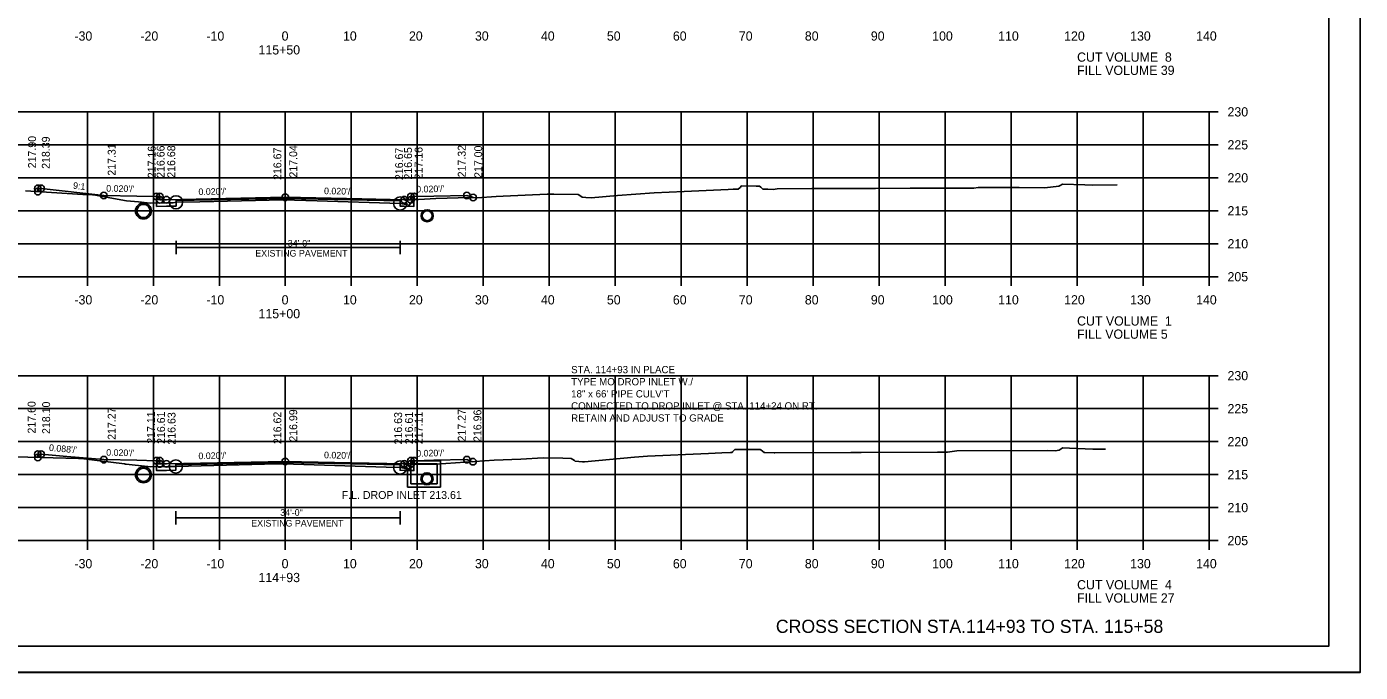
# Model space of a CAD drawing. Extents: x 1368968 to 1369915, y 377395 to 380381.
# Drawn here: x 1369712.6 to 1369914.7, y 378674.7 to 378772.6 of the extents above; entities that cross this region are included whole.
import ezdxf

# ---------------------------------------------------------------- set-up
doc = ezdxf.new("R2010")
doc.units = 0
for name, color, linetype in [('Default', 7, 'Continuous'), ('S_BORDER_NO_PLOT', 7, 'Continuous'), ('S_BREAKLINE_ANNOT', 7, 'Continuous'), ('S_BRIDGE', 7, 'Continuous'), ('S_BRIDGE_ANNOT', 7, 'Continuous'), ('S_CONTOUR_MAJOR', 7, 'Continuous'), ('S_CONTOUR_MINOR', 7, 'Continuous'), ('S_CROSS_DRAIN', 7, 'Continuous'), ('S_CTL_TABLE', 7, 'Continuous'), ('S_CURB_ANNOT', 7, 'Continuous'), ('S_DITCHLINE_ANNOT', 7, 'Continuous'), ('S_DROP_INLET', 7, 'Continuous'), ('S_EXIST_ROW_ANNOT', 7, 'Continuous'), ('S_EXISTING_ALIGNMENT_ANNOT', 7, 'Continuous'), ('S_FENCE', 7, 'Continuous')]:
    doc.layers.add(name, color=color, linetype=linetype)

msp = doc.modelspace()

# ---------------------------------------------------------------- linework, layer by layer
at = {"layer": 'Default'}
for p, q in [((1369735.22, 378746.24), (1369735.22, 378745.41)), ((1369735.18, 378706.19), (1369735.18, 378705.36)), ((1369770.78, 378703.31), (1369774.78, 378703.31)), ((1369770.28, 378702.81), (1369775.28, 378702.81))]:
    msp.add_line(p, q, dxfattribs=at)
at = {"layer": 'S_BORDER_NO_PLOT'}
for points in [[(1369732.27, 378746.86), (1369732.28, 378745.35), (1369733.78, 378745.38), (1369735.22, 378745.41), (1369735.22, 378746.24), (1369751.78, 378746.57), (1369769.19, 378746.22), (1369769.19, 378745.39), (1369769.78, 378745.38), (1369771.28, 378745.35), (1369771.29, 378746.86)], [(1369732.27, 378706.81), (1369732.28, 378705.3), (1369733.78, 378705.33), (1369735.18, 378705.36), (1369735.18, 378706.19), (1369751.78, 378706.52), (1369769.18, 378706.18), (1369769.18, 378705.35), (1369769.78, 378705.33), (1369771.28, 378705.3), (1369771.29, 378706.81)]]:
    msp.add_lwpolyline(points, dxfattribs=at)
at = {"layer": 'S_BREAKLINE_ANNOT'}
for p, q in [((1369891.78, 378734.7), (1369891.78, 378759.7)), ((1369893.18, 378759.7), (1369891.78, 378759.7)), ((1369893.18, 378754.7), (1369891.78, 378754.7)), ((1369893.18, 378749.7), (1369891.78, 378749.7)), ((1369893.18, 378744.7), (1369891.78, 378744.7)), ((1369893.18, 378739.7), (1369891.78, 378739.7)), ((1369611.78, 378734.7), (1369891.78, 378734.7)), ((1369721.78, 378733.3), (1369721.78, 378734.7)), ((1369731.78, 378733.3), (1369731.78, 378734.7)), ((1369741.78, 378733.3), (1369741.78, 378734.7)), ((1369751.78, 378733.3), (1369751.78, 378734.7)), ((1369761.78, 378733.3), (1369761.78, 378734.7)), ((1369771.78, 378733.3), (1369771.78, 378734.7)), ((1369781.78, 378733.3), (1369781.78, 378734.7)), ((1369791.78, 378733.3), (1369791.78, 378734.7)), ((1369801.78, 378733.3), (1369801.78, 378734.7)), ((1369811.78, 378733.3), (1369811.78, 378734.7)), ((1369821.78, 378733.3), (1369821.78, 378734.7)), ((1369831.78, 378733.3), (1369831.78, 378734.7)), ((1369841.78, 378733.3), (1369841.78, 378734.7)), ((1369851.78, 378733.3), (1369851.78, 378734.7)), ((1369861.78, 378733.3), (1369861.78, 378734.7)), ((1369871.78, 378733.3), (1369871.78, 378734.7)), ((1369881.78, 378733.3), (1369881.78, 378734.7)), ((1369891.78, 378733.3), (1369891.78, 378734.7)), ((1369893.18, 378734.7), (1369891.78, 378734.7)), ((1369891.78, 378694.7), (1369891.78, 378719.7)), ((1369893.18, 378719.7), (1369891.78, 378719.7)), ((1369893.18, 378714.7), (1369891.78, 378714.7)), ((1369893.18, 378709.7), (1369891.78, 378709.7)), ((1369893.18, 378704.7), (1369891.78, 378704.7)), ((1369893.18, 378699.7), (1369891.78, 378699.7)), ((1369611.78, 378694.7), (1369891.78, 378694.7)), ((1369721.78, 378693.3), (1369721.78, 378694.7)), ((1369731.78, 378693.3), (1369731.78, 378694.7)), ((1369741.78, 378693.3), (1369741.78, 378694.7)), ((1369751.78, 378693.3), (1369751.78, 378694.7)), ((1369761.78, 378693.3), (1369761.78, 378694.7)), ((1369771.78, 378693.3), (1369771.78, 378694.7)), ((1369781.78, 378693.3), (1369781.78, 378694.7)), ((1369791.78, 378693.3), (1369791.78, 378694.7)), ((1369801.78, 378693.3), (1369801.78, 378694.7)), ((1369811.78, 378693.3), (1369811.78, 378694.7)), ((1369821.78, 378693.3), (1369821.78, 378694.7)), ((1369831.78, 378693.3), (1369831.78, 378694.7)), ((1369841.78, 378693.3), (1369841.78, 378694.7)), ((1369851.78, 378693.3), (1369851.78, 378694.7)), ((1369861.78, 378693.3), (1369861.78, 378694.7)), ((1369871.78, 378693.3), (1369871.78, 378694.7)), ((1369881.78, 378693.3), (1369881.78, 378694.7)), ((1369891.78, 378693.3), (1369891.78, 378694.7)), ((1369893.18, 378694.7), (1369891.78, 378694.7))]:
    msp.add_line(p, q, dxfattribs=at)
at = {"layer": 'S_BRIDGE_ANNOT'}
for q in [(1369909.96, 378884.16), (1369593.78, 378678.7)]:
    msp.add_line((1369909.96, 378678.7), q, dxfattribs=at)
at = {"layer": 'S_CROSS_DRAIN'}
for p, q in [((1369735.22, 378739.12), (1369769.19, 378739.12)), ((1369735.18, 378698.15), (1369769.18, 378698.15))]:
    msp.add_line(p, q, dxfattribs=at)
at = {"layer": 'S_CTL_TABLE'}
for points in [[(1369712.41, 378747.72), (1369721.09, 378747.15), (1369722.55, 378747.11), (1369722.6, 378747.11), (1369723, 378747.06), (1369723.51, 378746.99), (1369727.72, 378746.23), (1369729.53, 378746.07), (1369731.31, 378745.86), (1369733.76, 378745.93), (1369734.77, 378745.9), (1369735.22, 378745.99), (1369738.81, 378746.07), (1369751.45, 378746.38), (1369756.6, 378746.22), (1369769.19, 378745.81), (1369770.12, 378745.63), (1369770.57, 378745.57), (1369770.75, 378745.8), (1369771.1, 378746.34), (1369773.74, 378746.5), (1369774.61, 378746.54), (1369779.7, 378746.72), (1369780.86, 378746.68), (1369783.76, 378746.87), (1369784.81, 378746.92), (1369791.45, 378747.24), (1369792.46, 378747.22), (1369796.14, 378747.19), (1369796.4, 378747.01), (1369796.75, 378746.74), (1369797.32, 378746.7), (1369798.15, 378746.66), (1369802.11, 378747.03), (1369807.68, 378747.41), (1369812.23, 378747.63), (1369818.92, 378747.94), (1369819.67, 378747.96), (1369820.42, 378747.99), (1369820.71, 378748.24), (1369820.91, 378748.47), (1369823.15, 378748.45), (1369823.67, 378748.42), (1369823.83, 378748.26), (1369824.17, 378748), (1369824.92, 378747.98), (1369825.71, 378747.94), (1369826.32, 378748.04), (1369831.56, 378748.06), (1369841.23, 378748.09), (1369846.46, 378748.11), (1369856.13, 378748.14), (1369856.78, 378748.24), (1369863, 378748.25), (1369866.88, 378748.18), (1369869, 378748.41), (1369869.22, 378748.55), (1369869.58, 378748.72), (1369872.96, 378748.62), (1369874.19, 378748.56), (1369877.87, 378748.61)], [(1369708.94, 378707.46), (1369720.45, 378707.14), (1369720.84, 378707.16), (1369724.05, 378706.76), (1369726.98, 378706.38), (1369727.42, 378706.33), (1369727.54, 378706.3), (1369727.64, 378706.29), (1369728.59, 378706.18), (1369731.41, 378705.86), (1369733.98, 378705.94), (1369735.18, 378705.94), (1369748.64, 378706.27), (1369751.45, 378706.34), (1369767.05, 378705.83), (1369769.18, 378705.77), (1369769.79, 378705.67), (1369769.91, 378705.64), (1369770.55, 378705.5), (1369770.6, 378705.52), (1369770.72, 378705.86), (1369770.78, 378706.28), (1369772.65, 378706.28), (1369774.62, 378706.28), (1369776.09, 378706.4), (1369783.42, 378706.87), (1369787.48, 378707.05), (1369790.88, 378707.22), (1369793.83, 378707.17), (1369795.1, 378707.16), (1369795.59, 378706.82), (1369795.72, 378706.72), (1369796.81, 378706.65), (1369797.1, 378706.63), (1369804.68, 378707.34), (1369806.66, 378707.48), (1369815.92, 378707.92), (1369817.94, 378708.01), (1369819.24, 378708.04), (1369819.48, 378708.06), (1369819.58, 378708.14), (1369819.92, 378708.53), (1369823.53, 378708.5), (1369823.77, 378708.49), (1369823.84, 378708.44), (1369824.34, 378708.06), (1369824.47, 378708.06), (1369825.85, 378708), (1369825.95, 378708.01), (1369837.49, 378708.06), (1369839.06, 378708.06), (1369850.61, 378708.1), (1369852.15, 378708.11), (1369853.58, 378708.33), (1369867.36, 378708.35), (1369868.45, 378708.33), (1369869.05, 378708.4), (1369869.52, 378708.7), (1369869.62, 378708.75), (1369870.64, 378708.72), (1369874.19, 378708.55), (1369876.08, 378708.57)]]:
    msp.add_lwpolyline(points, dxfattribs=at)
at = {"layer": 'S_CURB_ANNOT'}
for points in [[(1369714.27, 378747.6), (1369714.27, 378748.1), (1369714.77, 378748.1), (1369724.27, 378747.02), (1369729.27, 378746.92), (1369732.27, 378746.86), (1369732.62, 378746.86), (1369732.77, 378746.86), (1369732.78, 378746.36), (1369733.78, 378746.38), (1369751.78, 378746.74), (1369751.78, 378746.74), (1369763.4, 378746.51), (1369769.78, 378746.38), (1369770.78, 378746.36), (1369770.79, 378746.86), (1369770.94, 378746.86), (1369771.29, 378746.86), (1369774.29, 378746.92), (1369779.29, 378747.02), (1369780.13, 378746.74), (1369780.24, 378746.7)], [(1369714.27, 378707.31), (1369714.27, 378707.81), (1369714.77, 378707.81), (1369718.67, 378707.47), (1369724.27, 378706.97), (1369729.27, 378706.87), (1369732.27, 378706.81), (1369732.74, 378706.81), (1369732.77, 378706.81), (1369732.77, 378706.69), (1369732.78, 378706.31), (1369733.78, 378706.33), (1369751.78, 378706.69), (1369759.22, 378706.55), (1369769.78, 378706.33), (1369770.78, 378706.31), (1369770.79, 378706.81), (1369771.12, 378706.81), (1369771.29, 378706.81), (1369774.29, 378706.87), (1369779.29, 378706.97), (1369779.65, 378706.85), (1369780.22, 378706.66)]]:
    msp.add_lwpolyline(points, dxfattribs=at)
at = {"layer": 'S_DITCHLINE_ANNOT'}
for p, q in [((1369611.78, 378759.7), (1369891.78, 378759.7)), ((1369721.78, 378734.7), (1369721.78, 378759.7)), ((1369731.78, 378734.7), (1369731.78, 378759.7)), ((1369741.78, 378734.7), (1369741.78, 378759.7)), ((1369751.78, 378734.7), (1369751.78, 378759.7)), ((1369761.78, 378734.7), (1369761.78, 378759.7)), ((1369771.78, 378734.7), (1369771.78, 378759.7)), ((1369781.78, 378734.7), (1369781.78, 378759.7)), ((1369791.78, 378734.7), (1369791.78, 378759.7)), ((1369801.78, 378734.7), (1369801.78, 378759.7)), ((1369811.78, 378734.7), (1369811.78, 378759.7)), ((1369821.78, 378734.7), (1369821.78, 378759.7)), ((1369831.78, 378734.7), (1369831.78, 378759.7)), ((1369841.78, 378734.7), (1369841.78, 378759.7)), ((1369851.78, 378734.7), (1369851.78, 378759.7)), ((1369861.78, 378734.7), (1369861.78, 378759.7)), ((1369871.78, 378734.7), (1369871.78, 378759.7)), ((1369881.78, 378734.7), (1369881.78, 378759.7)), ((1369891.78, 378734.7), (1369891.78, 378759.7)), ((1369611.78, 378754.7), (1369891.78, 378754.7)), ((1369611.78, 378749.7), (1369891.78, 378749.7)), ((1369611.78, 378744.7), (1369891.78, 378744.7)), ((1369611.78, 378739.7), (1369891.78, 378739.7)), ((1369611.78, 378734.7), (1369891.78, 378734.7)), ((1369611.78, 378719.7), (1369891.78, 378719.7)), ((1369721.78, 378694.7), (1369721.78, 378719.7)), ((1369731.78, 378694.7), (1369731.78, 378719.7)), ((1369741.78, 378694.7), (1369741.78, 378719.7)), ((1369751.78, 378694.7), (1369751.78, 378719.7)), ((1369761.78, 378694.7), (1369761.78, 378719.7)), ((1369771.78, 378694.7), (1369771.78, 378719.7)), ((1369781.78, 378694.7), (1369781.78, 378719.7)), ((1369791.78, 378694.7), (1369791.78, 378719.7)), ((1369801.78, 378694.7), (1369801.78, 378719.7)), ((1369811.78, 378694.7), (1369811.78, 378719.7)), ((1369821.78, 378694.7), (1369821.78, 378719.7)), ((1369831.78, 378694.7), (1369831.78, 378719.7)), ((1369841.78, 378694.7), (1369841.78, 378719.7)), ((1369851.78, 378694.7), (1369851.78, 378719.7)), ((1369861.78, 378694.7), (1369861.78, 378719.7)), ((1369871.78, 378694.7), (1369871.78, 378719.7)), ((1369881.78, 378694.7), (1369881.78, 378719.7)), ((1369891.78, 378694.7), (1369891.78, 378719.7)), ((1369611.78, 378714.7), (1369891.78, 378714.7)), ((1369611.78, 378709.7), (1369891.78, 378709.7)), ((1369611.78, 378704.7), (1369891.78, 378704.7)), ((1369611.78, 378699.7), (1369891.78, 378699.7)), ((1369611.78, 378694.7), (1369891.78, 378694.7))]:
    msp.add_line(p, q, dxfattribs=at)
at = {"layer": 'S_DROP_INLET'}
msp.add_line((1369581.38, 378674.73), (1369914.71, 378674.73), dxfattribs=at)
for points in [[(1369581.37, 378888.06), (1369914.71, 378888.06), (1369914.71, 378674.72), (1369581.37, 378674.72)], [(1369827.7, 378884.16), (1369827.7, 378874.28), (1369863.43, 378874.28), (1369863.43, 378871.36), (1369886.63, 378871.36), (1369886.63, 378847.03), (1369909.96, 378847.03), (1369909.96, 378678.7), (1369593.78, 378678.7), (1369593.78, 378884.16)]]:
    msp.add_lwpolyline(points, close=True, dxfattribs=at)
for centre, radius in [((1369714.27, 378748.1), 0.5), ((1369714.27, 378747.6), 0.5), ((1369714.77, 378748.1), 0.5), ((1369724.27, 378747.02), 0.5), ((1369730.28, 378744.67), 1.21), ((1369732.27, 378746.86), 0.5), ((1369732.77, 378746.86), 0.5), ((1369732.78, 378746.36), 0.5), ((1369733.78, 378746.38), 0.5), ((1369733.78, 378746.38), 0.5), ((1369735.22, 378745.99), 1), ((1369751.78, 378746.74), 0.5), ((1369769.19, 378745.81), 1), ((1369769.78, 378746.38), 0.5), ((1369769.78, 378746.38), 0.5), ((1369770.78, 378746.36), 0.5), ((1369770.79, 378746.86), 0.5), ((1369771.29, 378746.86), 0.5), ((1369779.29, 378747.02), 0.5), ((1369780.24, 378746.7), 0.5), ((1369773.28, 378743.95), 0.917), ((1369714.27, 378707.81), 0.5), ((1369714.27, 378707.31), 0.5), ((1369714.77, 378707.81), 0.5), ((1369724.27, 378706.97), 0.5), ((1369779.29, 378706.97), 0.5), ((1369730.28, 378704.67), 1.21), ((1369732.27, 378706.81), 0.5), ((1369732.77, 378706.81), 0.5), ((1369732.78, 378706.31), 0.5), ((1369733.78, 378706.33), 0.5), ((1369733.78, 378706.33), 0.5), ((1369735.18, 378705.94), 1), ((1369751.78, 378706.69), 0.5), ((1369769.18, 378705.77), 1), ((1369769.78, 378706.33), 0.5), ((1369769.78, 378706.33), 0.5), ((1369770.78, 378706.31), 0.5), ((1369770.79, 378706.81), 0.5), ((1369771.29, 378706.81), 0.5), ((1369780.22, 378706.66), 0.5), ((1369773.25, 378704.07), 0.917)]:
    msp.add_circle(centre, radius, dxfattribs=at)
at = {"layer": 'S_EXIST_ROW_ANNOT'}
for p, q in [((1369735.22, 378738.12), (1369735.22, 378740.12)), ((1369769.19, 378738.12), (1369769.19, 378740.12)), ((1369769.78, 378706.33), (1369771.28, 378705.81)), ((1369769.78, 378705.81), (1369770.78, 378705.46)), ((1369770.28, 378702.81), (1369770.28, 378705.56)), ((1369770.78, 378703.31), (1369770.78, 378706.28)), ((1369770.78, 378705.31), (1369770.78, 378705.46)), ((1369770.94, 378706.65), (1369771.03, 378706.81)), ((1369770.94, 378706.65), (1369771.28, 378706.31)), ((1369775.28, 378706.81), (1369771.03, 378706.81)), ((1369774.78, 378706.31), (1369771.28, 378706.31)), ((1369771.28, 378705.31), (1369771.28, 378705.81)), ((1369774.78, 378705.29), (1369774.78, 378706.31)), ((1369774.78, 378703.31), (1369774.78, 378706.28)), ((1369775.28, 378705.35), (1369775.28, 378706.81)), ((1369775.28, 378702.81), (1369775.28, 378706.28)), ((1369735.18, 378697.15), (1369735.18, 378699.15)), ((1369769.18, 378697.15), (1369769.18, 378699.15))]:
    msp.add_line(p, q, dxfattribs=at)
msp.add_lwpolyline([(1369769.78, 378705.81), (1369769.78, 378706.33)], dxfattribs=at)
for centre, radius in [((1369730.28, 378744.67), 1), ((1369773.28, 378743.95), 0.75), ((1369730.28, 378704.67), 1), ((1369773.25, 378704.07), 0.75)]:
    msp.add_circle(centre, radius, dxfattribs=at)
at = {"layer": 'S_EXISTING_ALIGNMENT_ANNOT'}
for p, q in [((1369751.78, 378746.37), (1369751.78, 378756.37)), ((1369751.78, 378706.33), (1369751.78, 378716.33))]:
    msp.add_line(p, q, dxfattribs=at)

# ---------------------------------------------------------------- texts
at = {"layer": 'S_BRIDGE'}
for s, p in [('-30', (1369719.82, 378770.5)), ('-20', (1369729.82, 378770.5)), ('-10', (1369739.82, 378770.5)), ('0', (1369751.22, 378770.5)), ('10', (1369760.52, 378770.5)), ('20', (1369770.52, 378770.5)), ('30', (1369780.52, 378770.5)), ('40', (1369790.52, 378770.5)), ('50', (1369800.52, 378770.5)), ('60', (1369810.52, 378770.5)), ('70', (1369820.52, 378770.5)), ('80', (1369830.52, 378770.5)), ('90', (1369840.52, 378770.5)), ('100', (1369849.82, 378770.5)), ('110', (1369859.82, 378770.5)), ('120', (1369869.82, 378770.5)), ('130', (1369879.82, 378770.5)), ('140', (1369889.82, 378770.5)), ('115+50', (1369747.72, 378768.4)), ('CUT VOLUME  8', (1369871.78, 378767.3)), ('FILL VOLUME 39', (1369871.78, 378765.3)), ('230', (1369894.58, 378759)), ('225', (1369894.58, 378754)), ('220', (1369894.58, 378749)), ('215', (1369894.58, 378744)), ('210', (1369894.58, 378739)), ('205', (1369894.58, 378734)), ('-30', (1369719.82, 378730.5)), ('-20', (1369729.82, 378730.5)), ('-10', (1369739.82, 378730.5)), ('0', (1369751.22, 378730.5)), ('10', (1369760.52, 378730.5)), ('20', (1369770.52, 378730.5)), ('30', (1369780.52, 378730.5)), ('40', (1369790.52, 378730.5)), ('50', (1369800.52, 378730.5)), ('60', (1369810.52, 378730.5)), ('70', (1369820.52, 378730.5)), ('80', (1369830.52, 378730.5)), ('90', (1369840.52, 378730.5)), ('100', (1369849.82, 378730.5)), ('110', (1369859.82, 378730.5)), ('120', (1369869.82, 378730.5)), ('130', (1369879.82, 378730.5)), ('140', (1369889.82, 378730.5)), ('115+00', (1369747.72, 378728.4)), ('CUT VOLUME  1', (1369871.78, 378727.3)), ('FILL VOLUME 5', (1369871.78, 378725.3)), ('230', (1369894.58, 378719)), ('225', (1369894.58, 378714)), ('220', (1369894.58, 378709)), ('215', (1369894.58, 378704)), ('210', (1369894.58, 378699)), ('205', (1369894.58, 378694)), ('-30', (1369719.82, 378690.5)), ('-20', (1369729.82, 378690.5)), ('-10', (1369739.82, 378690.5)), ('0', (1369751.22, 378690.5)), ('10', (1369760.52, 378690.5)), ('20', (1369770.52, 378690.5)), ('30', (1369780.52, 378690.5)), ('40', (1369790.52, 378690.5)), ('50', (1369800.52, 378690.5)), ('60', (1369810.52, 378690.5)), ('70', (1369820.52, 378690.5)), ('80', (1369830.52, 378690.5)), ('90', (1369840.52, 378690.5)), ('100', (1369849.82, 378690.5)), ('110', (1369859.82, 378690.5)), ('120', (1369869.82, 378690.5)), ('130', (1369879.82, 378690.5)), ('140', (1369889.82, 378690.5)), ('114+93', (1369747.71, 378688.4)), ('CUT VOLUME  4', (1369871.78, 378687.3)), ('FILL VOLUME 27', (1369871.78, 378685.3))]:
    msp.add_text(s, height=1.4, dxfattribs=at).set_placement(p)
at = {"layer": 'S_CONTOUR_MAJOR'}
msp.add_text('F.L. DROP INLET 213.61', height=1.2, dxfattribs=at).set_placement((1369760.33, 378701.01))
at = {"layer": 'S_CONTOUR_MINOR'}
for s, height, p in [('STA. 114+93 IN PLACE', 1.1, (1369795.1, 378720.07)), ('TYPE MO DROP INLET W./ ', 1.1, (1369795.1, 378718.24)), ('18" x 66\' PIPE CULV\'T ', 1.1, (1369795.1, 378716.4)), ('CONNECTED TO DROP INLET @ STA. 114+24 ON RT. ', 1.1, (1369795.1, 378714.57)), ('RETAIN AND ADJUST TO GRADE ', 1.1, (1369795.1, 378712.74)), ('CROSS SECTION STA.114+93 TO STA. 115+58', 2, (1369826.13, 378680.7))]:
    msp.add_text(s, height=height, dxfattribs=at).set_placement(p)
at = {"layer": 'S_EXIST_ROW_ANNOT'}
for s, p in [('34\'-0"', (1369752.16, 378739.28)), ('EXISTING PAVEMENT', (1369747.23, 378737.76)), ('34\'-0"', (1369751.01, 378698.46)), ('EXISTING PAVEMENT', (1369746.62, 378696.83))]:
    msp.add_text(s, height=1, dxfattribs=at).set_placement(p)
at = {"layer": 'S_EXISTING_ALIGNMENT_ANNOT'}
for s, p in [('217.90', (1369714, 378751.14)), ('218.39', (1369716.08, 378751.06)), ('217.31', (1369726.07, 378750.02)), ('217.16', (1369732.13, 378749.64)), ('216.66', (1369733.48, 378749.69)), ('216.68', (1369735.09, 378749.71)), ('216.67', (1369751.18, 378749.37)), ('217.04', (1369753.58, 378749.74)), ('216.67', (1369769.63, 378749.36)), ('216.65', (1369770.98, 378749.43)), ('217.16', (1369772.58, 378749.47)), ('217.32', (1369779.12, 378749.77)), ('217.00', (1369781.62, 378749.68)), ('217.60', (1369713.93, 378710.93)), ('218.10', (1369716.13, 378710.86)), ('217.27', (1369726.07, 378709.97)), ('217.11', (1369732.02, 378709.38)), ('216.61', (1369733.54, 378709.35)), ('216.63', (1369735.14, 378709.25)), ('216.62', (1369751.18, 378709.33)), ('216.99', (1369753.58, 378709.69)), ('216.63', (1369769.48, 378709.28)), ('216.61', (1369771.12, 378709.31)), ('217.11', (1369772.58, 378709.33)), ('217.27', (1369779.12, 378709.73)), ('216.96', (1369781.5, 378709.65))]:
    msp.add_text(s, height=1.2, rotation=90, dxfattribs=at).set_placement(p)
at = {"layer": 'S_FENCE'}
for s, rotation, p in [('9:1', 353.5139, (1369719.57, 378748.06)), ("0.020'/'", 358.8543, (1369724.63, 378747.61)), ("0.020'/'", 1.1458, (1369738.62, 378747.08)), ("0.020'/'", 358.8542, (1369757.64, 378747.22)), ("0.020'/'", 1.1458, (1369771.63, 378747.47)), ("0.088'/'", 354.9887, (1369715.93, 378708.31)), ("0.020'/'", 358.8543, (1369724.63, 378707.57)), ("0.020'/'", 1.1458, (1369738.62, 378707.03)), ("0.020'/'", 358.8542, (1369757.64, 378707.18)), ("0.020'/'", 1.1457, (1369771.63, 378707.42))]:
    msp.add_text(s, height=1, rotation=rotation, dxfattribs=at).set_placement(p)

doc.saveas('drawing.dxf')
